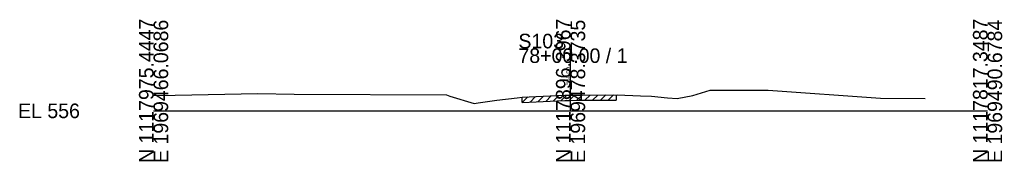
# Model space of a CAD drawing. Extents: x -26 to 163, y -10 to 45020.
# Drawn here: x -25.7 to 162.8, y 36990.3 to 37017.5 of the extents above; entities that cross this region are included whole.
import ezdxf

# ---------------------------------------------------------------- set-up
doc = ezdxf.new("R2010")
doc.units = 0
for name, color, linetype in [('RD_GPK_XS_Cell', 7, 'Continuous'), ('RD_XS_ExGround', 7, 'Continuous'), ('RD_XS_ExPaveRet', 7, 'Continuous'), ('RD_XS_TX_Elev_EX', 7, 'Continuous')]:
    doc.layers.add(name, color=color, linetype=linetype)

msp = doc.modelspace()

# ---------------------------------------------------------------- linework, layer by layer
at = {"layer": 'RD_GPK_XS_Cell'}
for p, q in [((80, 37000), (80, 37011.99)), ((0, 37000), (80, 37000)), ((80, 37000), (160, 37000))]:
    msp.add_line(p, q, dxfattribs=at)
at = {"layer": 'RD_XS_ExGround'}
for p, q in [((4.16, 37003.02), (20.02, 37003.35)), ((20.02, 37003.35), (26.97, 37003.2)), ((103.48, 37002.94), (106.8, 37003.95)), ((106.8, 37003.95), (117.94, 37004)), ((117.94, 37004), (139.47, 37002.45)), ((0, 37002.95), (4.16, 37003.02)), ((26.97, 37003.2), (56.17, 37003.05)), ((56.17, 37003.05), (56.85, 37002.84)), ((56.85, 37002.84), (61.52, 37001.4)), ((61.52, 37001.4), (62.3, 37001.54)), ((62.3, 37001.54), (65.85, 37002.08)), ((65.85, 37002.08), (69.74, 37002.49)), ((69.74, 37002.49), (70.73, 37002.61)), ((70.73, 37002.61), (77.4, 37002.93)), ((77.4, 37002.93), (78.88, 37002.99)), ((78.88, 37002.99), (80, 37003)), ((80, 37003), (82, 37003.03)), ((82, 37003.03), (88.92, 37003.06)), ((88.92, 37003.06), (93.42, 37002.89)), ((93.42, 37002.89), (95.55, 37002.8)), ((95.55, 37002.8), (98.57, 37002.49)), ((98.57, 37002.49), (100.44, 37002.34)), ((100.44, 37002.34), (103.48, 37002.94)), ((139.47, 37002.45), (148.02, 37002.38))]:
    msp.add_line(p, q, dxfattribs=at)
at = {"layer": 'RD_XS_ExPaveRet'}
for p, q in [((70.73, 37001.61), (71.78, 37002.66)), ((70.73, 37001.61), (70.73, 37002.61)), ((70.73, 37001.61), (77.4, 37001.93)), ((72.23, 37001.68), (73.28, 37002.73)), ((73.73, 37001.75), (74.78, 37002.8)), ((75.23, 37001.82), (76.28, 37002.87)), ((76.73, 37001.89), (77.78, 37002.94)), ((77.4, 37001.93), (78.88, 37001.99)), ((78.23, 37001.96), (79.26, 37002.99)), ((78.88, 37001.99), (80, 37002)), ((79.73, 37002), (80.74, 37003.01)), ((80, 37002), (82, 37002.03)), ((81.23, 37002.02), (82.24, 37003.03)), ((82, 37002.03), (88.78, 37002.06)), ((82.73, 37002.03), (83.74, 37003.04)), ((84.23, 37002.04), (85.24, 37003.04)), ((85.73, 37002.05), (86.74, 37003.05)), ((87.23, 37002.05), (88.24, 37003.06)), ((88.78, 37003.06), (88.78, 37002.06))]:
    msp.add_line(p, q, dxfattribs=at)

# ---------------------------------------------------------------- texts
at = {"layer": 'RD_GPK_XS_Cell'}
for s, p in [('N 1117975.4447', (0, 36990)), ('E 1969466.0686', (2.8, 36990)), ('N 1117896.3967', (80, 36990)), ('E 1969478.3735', (82.8, 36990)), ('N 1117817.3487', (160, 36990)), ('E 1969490.6784', (162.8, 36990))]:
    msp.add_text(s, height=2.8, rotation=90, dxfattribs=at).set_placement(p)
for s, p in [('S103', (70, 37011.99)), ('78+00.00 / 1', (70, 37009.19)), ('EL 556', (-26, 36998.6))]:
    msp.add_text(s, height=2.8, dxfattribs=at).set_placement(p)
at = {"layer": 'RD_XS_TX_Elev_EX'}
msp.add_text('559.00', height=0.8, rotation=90, dxfattribs=at).set_placement((79.9, 37005))

doc.saveas('drawing.dxf')
